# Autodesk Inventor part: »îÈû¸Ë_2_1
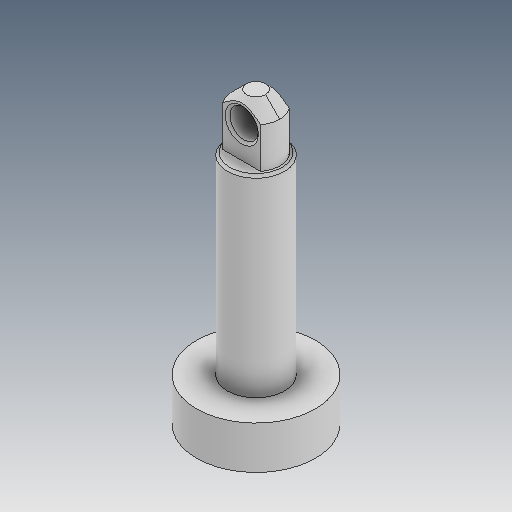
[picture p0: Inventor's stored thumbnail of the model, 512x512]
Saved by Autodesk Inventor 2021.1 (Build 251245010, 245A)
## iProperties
Created: 2019-04
Part Number: »îÈû¸Ë_2_1
Material: Ogólny
Document SubType Name: Modeling
Designer: user
Density: 1 g/cm^3
Appearance: Domyślna
Author: user
Revision Number: ÈÎºÎ
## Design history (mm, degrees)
feature "ÊäÈë1"
node "Bryła1"
